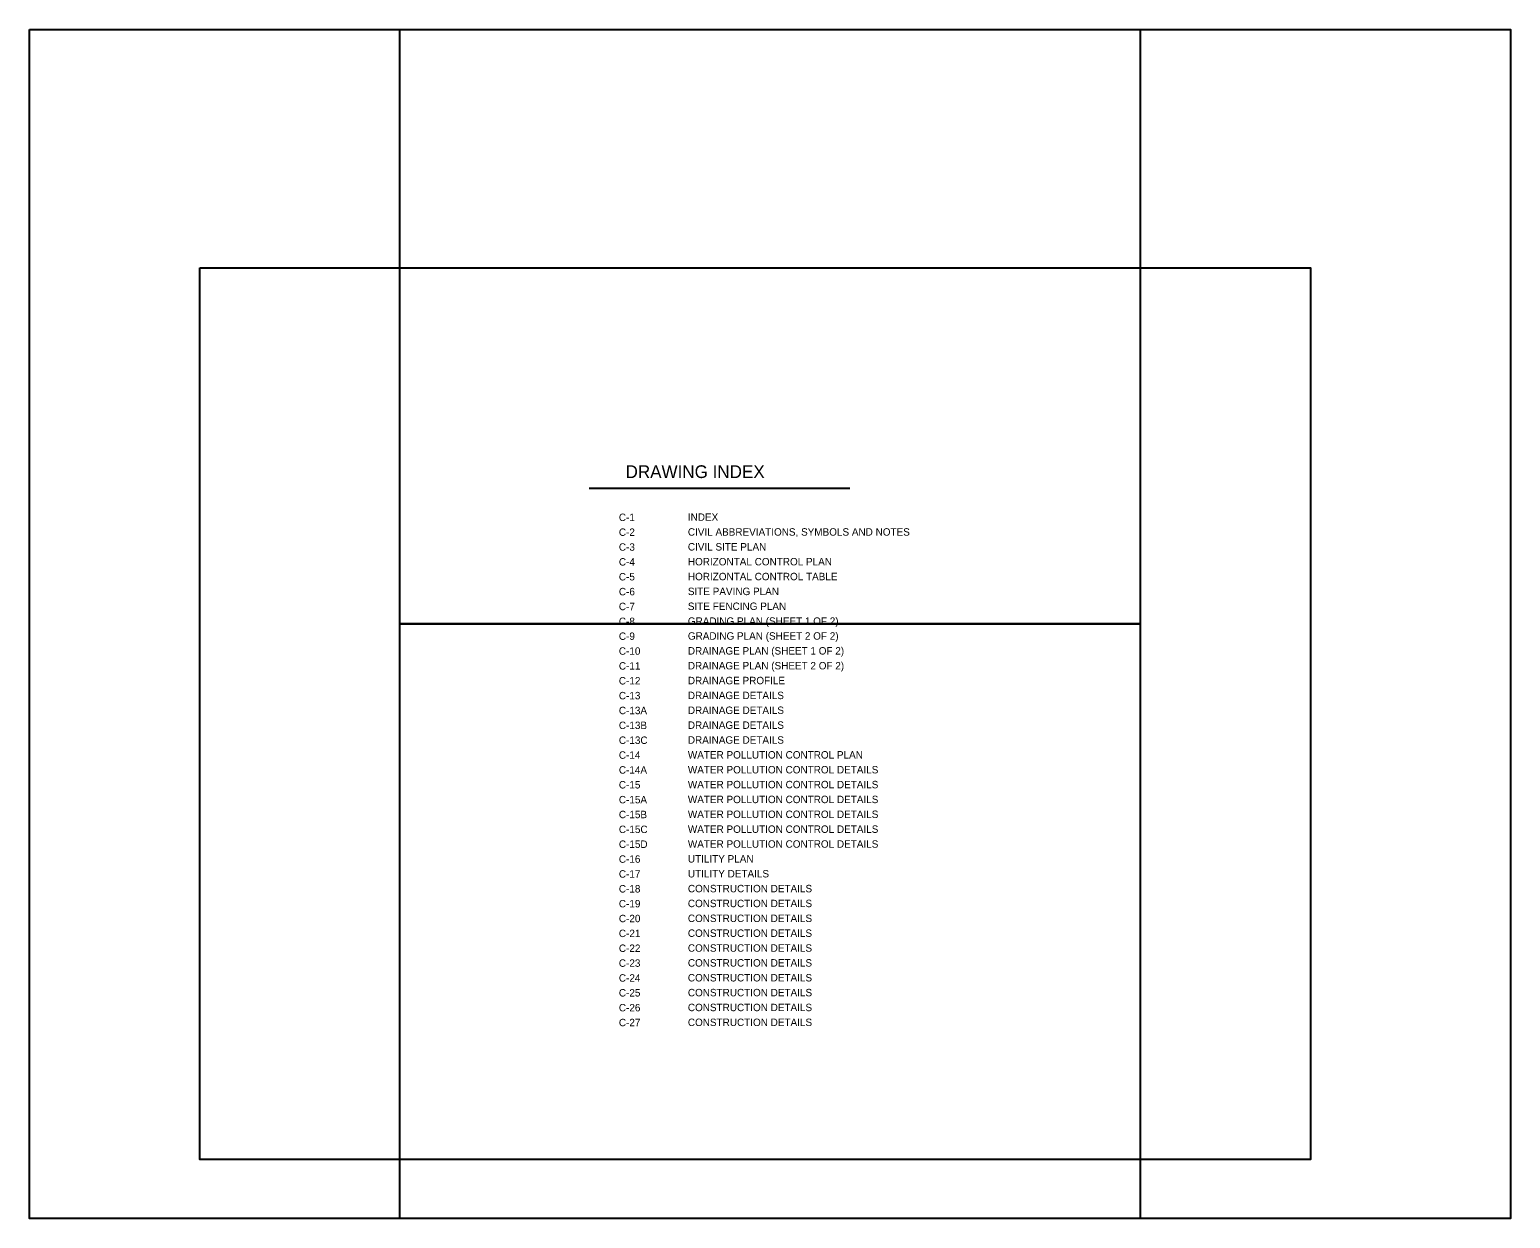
# Model space of a CAD drawing. Extents: x 6711682 to 6713077, y 1869405 to 1870525.
import ezdxf

# ---------------------------------------------------------------- set-up
doc = ezdxf.new("R2010")
doc.units = 0
for name, color, linetype in [('G-TTLB-VIEW', 7, 'Continuous'), ('Nongeo Data(60)', 7, 'Continuous'), ('Sheet Format(10)', 7, 'Continuous')]:
    doc.layers.add(name, color=color, linetype=linetype)

msp = doc.modelspace()

# ---------------------------------------------------------------- linework, layer by layer
at = {"layer": 'G-TTLB-VIEW'}
for points in [[(6711681.6, 1870524.7), (6713076.6, 1870524.7), (6713076.6, 1869404.7), (6711681.6, 1869404.7)], [(6712030.3, 1870524.7), (6712727.8, 1870524.7), (6712727.8, 1869964.7), (6712030.3, 1869964.7)], [(6711842, 1870300.1), (6712888.2, 1870300.1), (6712888.2, 1869460.1), (6711842, 1869460.1)], [(6712030.3, 1869964.7), (6712727.8, 1869964.7), (6712727.8, 1869404.7), (6712030.3, 1869404.7)]]:
    msp.add_lwpolyline(points, close=True, dxfattribs=at)
at = {"layer": 'Nongeo Data(60)'}
msp.add_line((6712208.6, 1870092.7), (6712454.3, 1870092.7), dxfattribs=at)

# ---------------------------------------------------------------- texts
msp.add_text('DRAWING INDEX', height=12, rotation=0, dxfattribs=at).set_placement((6712243, 1870102.2))
at = {"layer": 'Sheet Format(10)'}
for s, p in [('C-1', (6712236.7, 1870061.7)), ('INDEX', (6712301.7, 1870061.9)), ('C-2', (6712236.7, 1870047.7)), ('CIVIL ABBREVIATIONS, SYMBOLS AND NOTES', (6712301.7, 1870047.9)), ('C-3', (6712236.7, 1870033.7)), ('CIVIL SITE PLAN', (6712301.7, 1870033.9)), ('C-4', (6712236.7, 1870019.7)), ('HORIZONTAL CONTROL PLAN', (6712301.7, 1870019.9)), ('C-5', (6712236.7, 1870005.7)), ('HORIZONTAL CONTROL TABLE', (6712301.7, 1870005.9)), ('C-6', (6712236.7, 1869991.7)), ('SITE PAVING PLAN', (6712301.7, 1869991.9)), ('C-7', (6712236.7, 1869977.7)), ('SITE FENCING PLAN', (6712301.7, 1869977.9)), ('C-8', (6712236.7, 1869963.7)), ('GRADING PLAN (SHEET 1 OF 2)', (6712301.7, 1869963.9)), ('C-9', (6712236.7, 1869949.7)), ('GRADING PLAN (SHEET 2 OF 2)', (6712301.7, 1869949.9)), ('C-10', (6712236.7, 1869935.7)), ('DRAINAGE PLAN (SHEET 1 OF 2)', (6712301.7, 1869935.9)), ('C-11', (6712236.7, 1869921.7)), ('DRAINAGE PLAN (SHEET 2 OF 2)', (6712301.7, 1869921.9)), ('C-12', (6712236.7, 1869907.7)), ('DRAINAGE PROFILE', (6712301.7, 1869907.9)), ('C-13', (6712236.7, 1869893.7)), ('DRAINAGE DETAILS', (6712301.7, 1869893.9)), ('C-13A', (6712236.7, 1869879.7)), ('DRAINAGE DETAILS', (6712301.7, 1869879.9)), ('C-13B', (6712236.7, 1869865.7)), ('DRAINAGE DETAILS', (6712301.7, 1869865.9)), ('C-13C', (6712236.7, 1869851.7)), ('DRAINAGE DETAILS', (6712301.7, 1869851.9)), ('C-14', (6712236.7, 1869837.7)), ('WATER POLLUTION CONTROL PLAN', (6712301.7, 1869837.9)), ('C-14A', (6712236.7, 1869823.7)), ('WATER POLLUTION CONTROL DETAILS', (6712301.7, 1869823.9)), ('C-15', (6712236.7, 1869809.7)), ('WATER POLLUTION CONTROL DETAILS', (6712301.7, 1869809.9)), ('C-15A', (6712236.7, 1869795.7)), ('WATER POLLUTION CONTROL DETAILS', (6712301.7, 1869795.9)), ('C-15B', (6712236.7, 1869781.7)), ('WATER POLLUTION CONTROL DETAILS', (6712301.7, 1869781.9)), ('C-15C', (6712236.7, 1869767.7)), ('WATER POLLUTION CONTROL DETAILS', (6712301.7, 1869767.9)), ('C-15D', (6712236.7, 1869753.7)), ('WATER POLLUTION CONTROL DETAILS', (6712301.7, 1869753.9)), ('C-16', (6712236.7, 1869739.7)), ('UTILITY PLAN', (6712301.7, 1869739.9)), ('C-17', (6712236.7, 1869725.7)), ('UTILITY DETAILS', (6712301.7, 1869725.9)), ('C-18', (6712236.7, 1869711.7)), ('CONSTRUCTION DETAILS', (6712301.7, 1869711.9)), ('C-19', (6712236.7, 1869697.7)), ('CONSTRUCTION DETAILS', (6712301.7, 1869697.9)), ('C-20', (6712236.7, 1869683.7)), ('CONSTRUCTION DETAILS', (6712301.7, 1869683.9)), ('C-21', (6712236.7, 1869669.7)), ('CONSTRUCTION DETAILS', (6712301.7, 1869669.9)), ('C-22', (6712236.7, 1869655.7)), ('CONSTRUCTION DETAILS', (6712301.7, 1869655.9)), ('C-23', (6712236.7, 1869641.7)), ('CONSTRUCTION DETAILS', (6712301.7, 1869641.9)), ('C-24', (6712236.7, 1869627.7)), ('CONSTRUCTION DETAILS', (6712301.7, 1869627.9)), ('C-25', (6712236.7, 1869613.7)), ('CONSTRUCTION DETAILS', (6712301.7, 1869613.9)), ('C-26', (6712236.7, 1869599.7)), ('CONSTRUCTION DETAILS', (6712301.7, 1869599.9)), ('C-27', (6712236.7, 1869585.7)), ('CONSTRUCTION DETAILS', (6712301.7, 1869585.9))]:
    msp.add_text(s, height=7, dxfattribs=at).set_placement(p)

doc.saveas('drawing.dxf')
